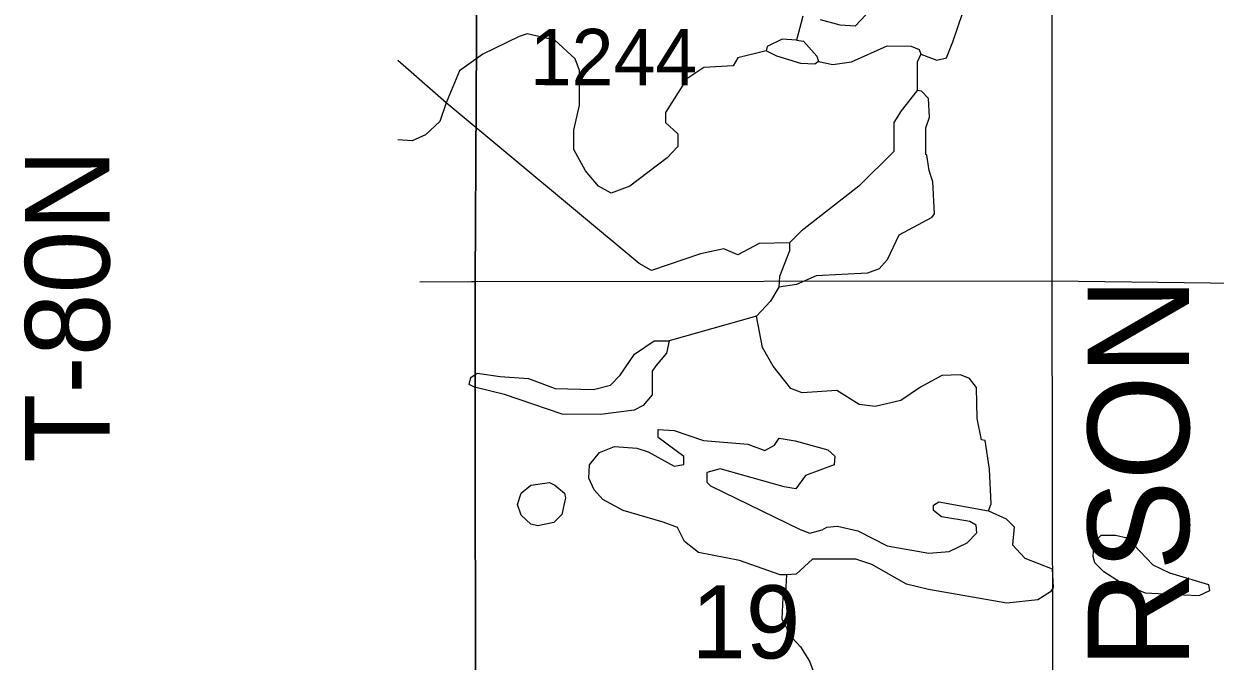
# Model space of a CAD drawing. Extents: x -1403959 to 81668, y -1400582 to 11018.
# Drawn here: x 6140.6 to 6345.3, y 9146 to 9255.5 of the extents above; entities that cross this region are included whole.
import ezdxf

# ---------------------------------------------------------------- set-up
doc = ezdxf.new("R2010")
doc.units = 0
for name, color, linetype in [('tdCoCityStreetMajor', 7, 'Continuous'), ('tdCoCityStreetMinor', 7, 'Continuous'), ('tdCoClipBndry', 7, 'Continuous'), ('tdCoCoBndryPart', 7, 'Continuous'), ('tdCoSectLinePart', 7, 'Continuous'), ('tdCoShieldCoRte', 7, 'Continuous'), ('tdCoStrucSecFHWANum', 7, 'Continuous'), ('tdCoSurfBitum', 7, 'Continuous')]:
    doc.layers.add(name, color=color, linetype=linetype)

msp = doc.modelspace()

# ---------------------------------------------------------------- linework, layer by layer
at = {"layer": 'tdCoCityStreetMajor'}
for points in [[(6218.6, 9304.44), (6218.13, 9211.25)], [(6317.27, 9211.34), (6317.32, 9304.88)], [(6208.62, 9211.18), (6217.46, 9211.25), (6218.13, 9211.25)], [(6218.13, 9211.25), (6317.27, 9211.34)], [(6218.13, 9211.25), (6218.14, 9115.55)], [(6317.27, 9211.34), (6362.64, 9210.75)], [(6317.41, 9113.5), (6317.27, 9211.34)]]:
    msp.add_lwpolyline(points, dxfattribs=at)
at = {"layer": 'tdCoCityStreetMinor'}
msp.add_lwpolyline([(6218.14, 9115.55), (6218.13, 9211.25), (6218.6, 9304.44)], dxfattribs=at)
at = {"layer": 'tdCoClipBndry'}
msp.add_lwpolyline([(6778.71, 10085.37), (6705.52, 10085.58), (6607.92, 10086.06), (6510.34, 10086.5), (6412.84, 10087.26), (6315.56, 10087.31), (6215.78, 10087.65), (6215.21, 10012.23), (6215.81, 9994.41), (6217.04, 9970.57), (6217.41, 9896.62), (6217.06, 9848.03), (6217.62, 9799.5), (6216.78, 9702.88), (6218.33, 9606.68), (6218.57, 9510.16), (6218.52, 9404.76), (6218.61, 9307.34), (6218.13, 9211.25), (6218.14, 9113.22), (6218.14, 9016.46), (6218.02, 8919.84), (6217.44, 8816.34), (6216.99, 8719.3)], dxfattribs=at)
at = {"layer": 'tdCoSurfBitum'}
for points in [[(6274.39, 9256.81), (6273.31, 9252.69), (6274.53, 9252.53), (6276.81, 9249.93), (6277.12, 9249.01), (6279.56, 9248.54), (6282.77, 9248.99), (6288.88, 9251.72), (6293.01, 9251.7), (6294.38, 9251.08), (6294.68, 9250.32), (6297.43, 9249.24), (6299.11, 9249.69), (6300.19, 9252.44), (6301.88, 9257.47)], [(6285.24, 9257.07), (6283.4, 9255.09), (6280.8, 9255.26), (6277.45, 9256.19)], [(6268.11, 9250.88), (6263.22, 9249.67), (6262.45, 9248.3), (6257.41, 9248.02), (6254.5, 9246.04), (6250.82, 9240.26), (6250.81, 9238.58), (6252.94, 9236.58), (6252.94, 9234.45), (6251.1, 9232.47), (6244.67, 9227.61), (6241.46, 9226.4), (6239.32, 9227.63), (6237.04, 9230.23), (6235.07, 9233.9), (6235.08, 9237.26), (6236.01, 9241.53), (6236.03, 9247.49), (6235.28, 9249.47), (6231.78, 9252.69), (6227.05, 9253.78), (6225.67, 9253.33), (6219.4, 9250.3), (6215.42, 9247.41), (6213.11, 9241.93), (6212.03, 9238.72), (6209.58, 9236.44), (6207.28, 9235.38), (6204.83, 9235.56)], [(6273.31, 9252.69), (6270.87, 9252.85), (6268.27, 9251.64), (6268.11, 9250.88)], [(6277.12, 9249.01), (6276.5, 9248.56), (6274.06, 9248.72), (6269.94, 9249.95), (6268.11, 9250.88)], [(6272.12, 9217.89), (6266.93, 9217.75), (6263.25, 9215.78), (6260.81, 9216.86), (6256.84, 9215.96), (6248.43, 9213.09), (6246.3, 9214.32), (6213.11, 9241.93), (6204.83, 9249.2)], [(6294.68, 9250.32), (6294.07, 9248.95), (6294.05, 9244.06)], [(6294.05, 9244.06), (6291.29, 9240.56), (6290.06, 9238.58), (6290.04, 9233.54), (6284.06, 9227.61), (6274.11, 9219.86), (6272.12, 9217.89)], [(6296.57, 9222.22), (6297.03, 9222.83), (6296.74, 9228.33), (6296.14, 9230.32), (6295.69, 9232.91), (6295.54, 9233.07), (6295.55, 9237.65), (6296.17, 9239.48), (6296.03, 9242.68), (6294.81, 9243.91), (6294.05, 9244.06)], [(6296.57, 9222.22), (6290.91, 9219.19), (6288.91, 9214.92), (6287.53, 9213.4), (6285.54, 9212.65), (6276.68, 9212.22), (6273.31, 9210.71), (6270.26, 9210.26)], [(6272.12, 9217.89), (6272.11, 9216.51), (6270.42, 9212.09), (6270.26, 9210.26)], [(6270.26, 9210.26), (6268.88, 9207.82), (6266.42, 9205.24)], [(6266.42, 9205.24), (6251.44, 9201.02)], [(6306.31, 9171.81), (6306.78, 9173.03), (6306.49, 9178.98), (6305.75, 9183.87), (6305.13, 9184.02), (6304.38, 9187.69), (6304.25, 9193.03), (6303.03, 9194.57), (6301.51, 9195.18), (6298.3, 9195.04), (6294.63, 9193.07), (6291.26, 9190.79), (6286.83, 9189.74), (6284.08, 9190.06), (6280.27, 9192.51), (6274.32, 9192.08), (6272.34, 9192.85), (6269.29, 9196.68), (6267.47, 9199.89), (6266.42, 9205.24)], [(6251.44, 9201.02), (6250.98, 9198.88), (6249.14, 9196.75), (6248.52, 9195.84), (6248.51, 9191.72), (6246.98, 9189.89), (6245.45, 9189.13), (6239.64, 9188.39), (6233.07, 9188.42), (6223.16, 9191.81), (6217.97, 9193.05), (6217.06, 9193.52), (6217.37, 9194.74), (6218.44, 9195.49), (6222.41, 9194.87), (6227.29, 9194.55), (6231.87, 9192.85), (6238.43, 9192.67), (6241.34, 9193.42), (6243.02, 9195.1), (6245.48, 9198.75), (6248.85, 9201.03), (6251.44, 9201.02)], [(6271.61, 9160.79), (6270.54, 9160.8), (6263.53, 9163.27), (6256.51, 9164.67), (6254.07, 9166.51), (6252.86, 9168.95), (6250.42, 9169.88), (6243.55, 9171.89), (6240.05, 9173.73), (6238.53, 9175.42), (6237.62, 9177.41), (6237.78, 9179.7), (6239.47, 9181.83), (6242.06, 9182.89), (6245.88, 9182.57), (6247.86, 9181.95), (6252.28, 9179.49), (6253.96, 9179.79), (6253.97, 9181.16), (6249.55, 9184.39), (6249.56, 9185.76), (6252.31, 9185.6), (6257.34, 9183.9), (6264.97, 9183.26), (6267.87, 9182.18), (6269.55, 9183.09), (6270.32, 9184.31), (6273.07, 9183.84), (6278.71, 9182.29), (6279.93, 9181.22), (6279.77, 9179.69), (6274.88, 9177.88), (6273.19, 9175.59), (6271.21, 9175.91), (6260.22, 9179), (6257.93, 9178.4), (6257.92, 9176.72), (6258.53, 9176.11), (6273.93, 9168.57), (6275.61, 9167.95), (6277.75, 9168.55), (6278.51, 9169.01), (6280.34, 9169.16), (6283.85, 9168.38), (6288.88, 9165.77), (6296.06, 9164.52), (6299.57, 9164.81), (6302.63, 9166.32), (6304.31, 9168), (6304.17, 9169.37), (6303.1, 9169.99), (6298.22, 9170.77), (6296.85, 9171.84), (6296.85, 9172.76), (6297.77, 9173.36), (6306.31, 9171.81), (6309.36, 9170.42), (6310.73, 9169.04), (6310.42, 9165.99), (6312.55, 9163.69), (6317.27, 9161.84), (6317.41, 9158.64), (6316.95, 9157.87), (6314.81, 9156.51), (6309.46, 9155.92), (6296.03, 9158.26), (6292.22, 9159.19), (6286.28, 9162.57), (6283.53, 9163.49), (6276.05, 9163.52), (6273.29, 9160.94), (6271.61, 9160.79), (6271.45, 9157.74), (6270.99, 9156.98), (6270.82, 9153.16), (6271.58, 9151.78), (6271.88, 9150.71), (6274.01, 9148.42), (6275.53, 9145.97), (6276.28, 9143.98)], [(6228.88, 9169.2), (6227.66, 9169.51), (6225.99, 9171.04), (6225.38, 9172.87), (6226, 9174.86), (6227.69, 9176.22), (6230.9, 9176.67), (6231.81, 9176.21), (6233.48, 9174.83), (6233.63, 9174.06), (6233.01, 9171.17), (6231.63, 9169.8), (6228.88, 9169.2)], [(6339.86, 9157.33), (6333.29, 9157.66), (6329.17, 9159.35), (6326.13, 9161.35), (6324.61, 9162.88), (6324.3, 9163.95), (6324.47, 9166.39), (6325.69, 9167.61), (6328.14, 9167.6), (6330.12, 9167.14), (6334.53, 9162.54), (6337.43, 9161.16), (6344.14, 9159.15), (6344.29, 9158.08), (6342.45, 9157.17), (6339.86, 9157.33)]]:
    msp.add_lwpolyline(points, dxfattribs=at)

# ---------------------------------------------------------------- texts
at = {"layer": 'tdCoCoBndryPart'}
msp.add_text('JEFFERSON', height=17.411, rotation=89.9889, dxfattribs=at).set_placement((6340.76, 9073.54))
at = {"layer": 'tdCoSectLinePart'}
msp.add_text('19', height=12.575, rotation=359.9883, dxfattribs=at).set_placement((6255.26, 9146.44))
at = {"layer": 'tdCoShieldCoRte'}
msp.add_text('1244', height=9.673, rotation=359.9944, dxfattribs=at).set_placement((6227.49, 9244.97))
at = {"layer": 'tdCoStrucSecFHWANum'}
msp.add_text('T-80N', height=14.509, rotation=90.0065, dxfattribs=at).set_placement((6155.28, 9180.07))

doc.saveas('drawing.dxf')
